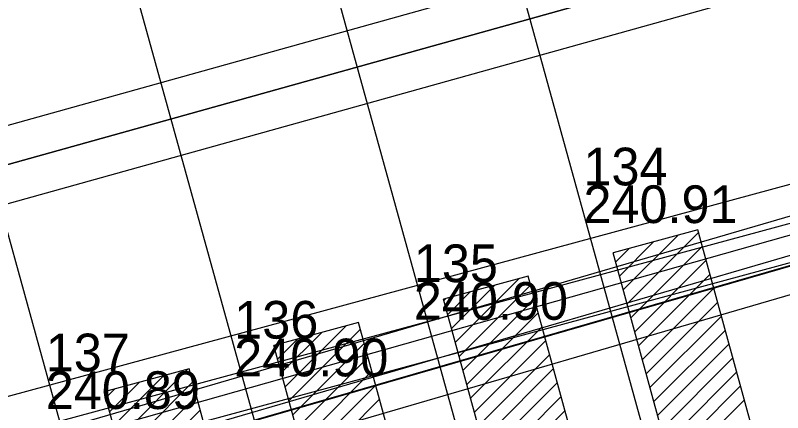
# Model space of a CAD drawing. Extents: x -599432 to -598680, y -1159407 to -1158632.
# Drawn here: x -599029.29 to -599023.18, y -1158877.07 to -1158873.91 of the extents above; entities that cross this region are included whole.
import ezdxf

# ---------------------------------------------------------------- set-up
doc = ezdxf.new("R2010")
doc.units = 0
for name, color, linetype in [('0004 VY - Body podrobné', 7, 'Continuous'), ('0005 VY - Body podrobné - čísla', 7, 'Continuous'), ('0006 VY - Body podrobné - výšky', 7, 'Continuous'), ('0063 ZA - Doprava - vodorovné značení', 7, 'Continuous'), ('0066 ZA - Doprava - DPMB - koleje', 7, 'Continuous'), ('0202 PV - MUNI', 7, 'Continuous'), ('0203 PV - MUNI - chránička', 7, 'Continuous'), ('0454 PV - O2 - kabel zaměřený', 7, 'Continuous'), ('0530 PV - T-mobile - optické kabely', 7, 'Continuous'), ('0552 PV - NETBOX - vedení', 7, 'Continuous'), ('0553 PV - NETBOX - chranička', 7, 'Continuous'), ('0650 PV - BKOM - buňky', 7, 'Continuous'), ('0652 PV - BKOM - kabely bez rozlišení', 7, 'Continuous'), ('0704 PV - ČD - kabely', 7, 'Continuous')]:
    doc.layers.add(name, color=color, linetype=linetype)

msp = doc.modelspace()

# ---------------------------------------------------------------- linework, layer by layer
at = {"layer": '0004 VY - Body podrobné'}
for p, q in [((-599024.77, -1158875.26), (-599024.77, -1158875.26)), ((-599026.12, -1158876.03), (-599026.12, -1158876.03)), ((-599027.55, -1158876.48), (-599027.55, -1158876.48)), ((-599029.05, -1158876.74), (-599029.05, -1158876.74))]:
    msp.add_line(p, q, dxfattribs=at)
at = {"layer": '0063 ZA - Doprava - vodorovné značení'}
for p, q in [((-599023.8584, -1158875.6129), (-599024.5336, -1158875.7973)), ((-599024.453, -1158876.0924), (-599024.0167, -1158875.6561)), ((-599024.4227, -1158876.2035), (-599023.8527, -1158875.6335)), ((-599022.5886, -1158880.2609), (-599023.8584, -1158875.6129)), ((-599024.4834, -1158875.9813), (-599024.2113, -1158875.7093)), ((-599024.5137, -1158875.8702), (-599024.4059, -1158875.7624)), ((-599024.3923, -1158876.3146), (-599023.8224, -1158875.7446)), ((-599023.2639, -1158880.4453), (-599024.5336, -1158875.7973)), ((-599024.362, -1158876.4256), (-599023.792, -1158875.8557)), ((-599024.3316, -1158876.5367), (-599023.7617, -1158875.9668)), ((-599025.2089, -1158875.9818), (-599025.8841, -1158876.1662)), ((-599025.7901, -1158876.5104), (-599025.2812, -1158876.0015)), ((-599023.9392, -1158880.6298), (-599025.2089, -1158875.9818)), ((-599025.8205, -1158876.3994), (-599025.4758, -1158876.0547)), ((-599025.7598, -1158876.6215), (-599025.1898, -1158876.0516)), ((-599024.3013, -1158876.6478), (-599023.7314, -1158876.0778)), ((-599025.8508, -1158876.2883), (-599025.6704, -1158876.1079)), ((-599024.6144, -1158880.8143), (-599025.8841, -1158876.1662)), ((-599025.8812, -1158876.1772), (-599025.865, -1158876.161)), ((-599025.7294, -1158876.7326), (-599025.1595, -1158876.1626)), ((-599024.271, -1158876.7589), (-599023.701, -1158876.1889)), ((-599025.6991, -1158876.8437), (-599025.1291, -1158876.2737)), ((-599024.2406, -1158876.8699), (-599023.6707, -1158876.3)), ((-599026.5594, -1158876.3507), (-599027.2347, -1158876.5352)), ((-599027.1447, -1158876.8644), (-599026.6579, -1158876.3776)), ((-599025.2897, -1158880.9987), (-599026.5594, -1158876.3507)), ((-599025.6687, -1158876.9547), (-599025.0988, -1158876.3848)), ((-599027.1751, -1158876.7533), (-599026.8525, -1158876.4308)), ((-599027.1144, -1158876.9755), (-599026.5444, -1158876.4056)), ((-599024.2103, -1158876.981), (-599023.6403, -1158876.4111)), ((-599027.2054, -1158876.6423), (-599027.0471, -1158876.4839)), ((-599027.084, -1158877.0866), (-599026.5141, -1158876.5166)), ((-599025.6384, -1158877.0658), (-599025.0685, -1158876.4959)), ((-599025.9649, -1158881.1832), (-599027.2347, -1158876.5352)), ((-599024.1799, -1158877.0921), (-599023.61, -1158876.5221)), ((-599027.0537, -1158877.1977), (-599026.4837, -1158876.6277)), ((-599025.6081, -1158877.1769), (-599025.0381, -1158876.6069)), ((-599024.1496, -1158877.2032), (-599023.5796, -1158876.6332)), ((-599027.9099, -1158876.7196), (-599028.5852, -1158876.9041)), ((-599028.4812, -1158877.2848), (-599027.9183, -1158876.7219)), ((-599026.6402, -1158881.3676), (-599027.9099, -1158876.7196)), ((-599027.0233, -1158877.3087), (-599026.4534, -1158876.7388)), ((-599025.5777, -1158877.288), (-599025.0078, -1158876.718)), ((-599024.1192, -1158877.3143), (-599023.5493, -1158876.7443)), ((-599028.5115, -1158877.1737), (-599028.1129, -1158876.7751)), ((-599028.5722, -1158876.9516), (-599028.502, -1158876.8814)), ((-599028.5419, -1158877.0627), (-599028.3075, -1158876.8282)), ((-599028.4508, -1158877.3959), (-599027.8809, -1158876.8259)), ((-599026.993, -1158877.4198), (-599026.423, -1158876.8499)), ((-599025.5474, -1158877.399), (-599024.9774, -1158876.8291)), ((-599024.0889, -1158877.4253), (-599023.5189, -1158876.8554)), ((-599027.3154, -1158881.5521), (-599028.5852, -1158876.9041)), ((-599028.4205, -1158877.507), (-599027.8505, -1158876.937)), ((-599025.517, -1158877.5101), (-599024.9471, -1158876.9402)), ((-599026.9627, -1158877.5309), (-599026.3927, -1158876.9609)), ((-599024.0586, -1158877.5364), (-599023.4886, -1158876.9665)), ((-599028.3901, -1158877.618), (-599027.8202, -1158877.0481)), ((-599025.4867, -1158877.6212), (-599024.9167, -1158877.0513))]:
    msp.add_line(p, q, dxfattribs=at)
at = {"layer": '0066 ZA - Doprava - DPMB - koleje'}
for p, q in [((-599026.9947, -1158867.4391), (-599013.0005, -1158918.0205)), ((-599028.37, -1158867.8196), (-599014.3759, -1158918.401)), ((-599029.8529, -1158868.2298), (-599015.8588, -1158918.8113)), ((-599031.2942, -1158868.6286), (-599017.3, -1158919.21))]:
    msp.add_line(p, q, dxfattribs=at)
at = {"layer": '0202 PV - MUNI'}
msp.add_lwpolyline([(-599146.6366, -1158922.9878), (-599125.8483, -1158917.7447), (-599099.1764, -1158910.8285), (-599079.1004, -1158904.889), (-599063.7152, -1158899.846), (-599061.634, -1158898.4051), (-599061.0656, -1158896.468), (-599061.7781, -1158890.9687), (-599061.2017, -1158889.9281), (-599056.1907, -1158887.5907), (-599053.9174, -1158887.4786), (-599048.5222, -1158885.3494), (-599047.3855, -1158884.4528), (-599040.0211, -1158881.2029), (-599032.6727, -1158878.6013), (-599020.5455, -1158875.0632), (-599018.4963, -1158874.7671), (-599015.6546, -1158876.8083), (-599014.9422, -1158877.8009)], dxfattribs=at)
at = {"layer": '0203 PV - MUNI - chránička'}
for p, q in [((-599032.7567, -1158878.3133), (-599020.6295, -1158874.7752)), ((-599032.5887, -1158878.8893), (-599020.4615, -1158875.3512))]:
    msp.add_line(p, q, dxfattribs=at)
at = {"layer": '0454 PV - O2 - kabel zaměřený'}
for points in [[(-599065.99, -1158901.17), (-599063.3, -1158900.18), (-599061.65, -1158898.45), (-599061.04, -1158896.51), (-599061.91, -1158890.95), (-599061.26, -1158889.87), (-599056.07, -1158887.58), (-599053.91, -1158887.47), (-599052.4, -1158886.85), (-599049.09, -1158885.94), (-599048.46, -1158885.4), (-599047.47, -1158884.55), (-599040.18, -1158881.35), (-599032.72, -1158878.67), (-599020.59, -1158875.17), (-599018.58, -1158874.88), (-599016.36, -1158876.44), (-599015.76, -1158876.86), (-599014.99, -1158877.89), (-599012.08, -1158888.14), (-599011.3, -1158889.38), (-599007.9, -1158892.89), (-599006.6, -1158893.35), (-598996.83, -1158890.81)], [(-599032.72, -1158878.67), (-599020.59, -1158875.17)]]:
    msp.add_lwpolyline(points, dxfattribs=at)
at = {"layer": '0530 PV - T-mobile - optické kabely'}
msp.add_lwpolyline([(-599020.585, -1158875.165), (-599032.721, -1158878.667)], dxfattribs=at)
at = {"layer": '0552 PV - NETBOX - vedení'}
msp.add_lwpolyline([(-599006.06, -1158869.51), (-599006.06, -1158869.51), (-599007.15, -1158869.17), (-599007.15, -1158869.17), (-599008.89, -1158870.73), (-599009.02, -1158871.08), (-599010.62, -1158871.57), (-599015.34, -1158873.36), (-599021.01, -1158874.99), (-599029.72, -1158877.35), (-599032.35, -1158878.18), (-599038.52, -1158879.88), (-599044.56, -1158881.49), (-599050.4, -1158884.03), (-599052.74, -1158885.29), (-599055.15, -1158886.37), (-599057.94, -1158887.57), (-599060.68, -1158888.43), (-599062.55, -1158889.31)], dxfattribs=at)
at = {"layer": '0553 PV - NETBOX - chranička'}
msp.add_lwpolyline([(-599015.4348, -1158873.0751), (-599021.0907, -1158874.701), (-599029.8044, -1158877.0621), (-599032.435, -1158877.8922), (-599038.5985, -1158879.5904), (-599044.659, -1158881.2059), (-599050.53, -1158883.7594), (-599053.1483, -1158885.1442), (-599055.2706, -1158886.0953), (-599058.0445, -1158887.2884), (-599060.7893, -1158888.1499), (-599062.6777, -1158889.0386), (-599062.4223, -1158889.5814), (-599060.5707, -1158888.7101), (-599057.8355, -1158887.8516), (-599055.0294, -1158886.6447), (-599052.3317, -1158885.4358), (-599050.27, -1158884.3006), (-599044.461, -1158881.7741), (-599038.4415, -1158880.1696), (-599032.265, -1158878.4678), (-599029.6356, -1158877.6379), (-599020.9293, -1158875.279), (-599015.2452, -1158873.6449)], dxfattribs=at)
at = {"layer": '0650 PV - BKOM - buňky'}
for p, q in [((-599034.191, -1158876.131), (-599020.461, -1158872.301)), ((-599034.191, -1158876.131), (-599020.461, -1158872.301)), ((-599034.029, -1158876.709), (-599020.299, -1158872.879)), ((-599034.029, -1158876.709), (-599020.299, -1158872.879))]:
    msp.add_line(p, q, dxfattribs=at)
at = {"layer": '0652 PV - BKOM - kabely bez rozlišení'}
for points in [[(-599019.95, -1158872.38), (-599020.38, -1158872.59), (-599034.11, -1158876.42), (-599034.75, -1158875.39), (-599039.03, -1158861.54), (-599042.74, -1158848.47), (-599042.28, -1158847.4), (-599041.79, -1158847.4)], [(-599069.54, -1158906.27), (-599056.01, -1158902.46), (-599042.94, -1158898.82), (-599036.88, -1158897.21), (-599035.9, -1158896.65), (-599035.19, -1158895.15), (-599033.43, -1158892.94), (-599032.55, -1158892.85), (-599032.38, -1158891.47), (-599031.43, -1158887.7), (-599033.39, -1158880.98), (-599034.34, -1158877.53), (-599034.11, -1158876.42), (-599020.38, -1158872.59), (-599019.95, -1158872.38), (-599019.48, -1158873.04), (-599018.91, -1158874.17), (-599016.73, -1158875.93), (-599015.62, -1158876.75), (-599013.57, -1158877.37), (-599011.16, -1158877.03), (-599007.55, -1158875.71), (-599006.793, -1158874.464)]]:
    msp.add_lwpolyline(points, dxfattribs=at)
at = {"layer": '0704 PV - ČD - kabely'}
msp.add_lwpolyline([(-598961.1998, -1158881.213), (-599006.8409, -1158893.8814), (-599007.9998, -1158893.3892), (-599012.4449, -1158888.2457), (-599014.7944, -1158877.5617), (-599015.5723, -1158876.5616), (-599018.4457, -1158874.6248), (-599020.4301, -1158874.8947), (-599032.7968, -1158878.3872), (-599047.1639, -1158884.134), (-599048.6403, -1158885.0865), (-599049.561, -1158885.3882), (-599050.6564, -1158886.3724), (-599052.3709, -1158886.6423), (-599054.1807, -1158887.3884), (-599056.3556, -1158887.4043), (-599061.2213, -1158889.6983), (-599062.0071, -1158890.8333), (-599061.1578, -1158896.5405), (-599061.8246, -1158898.4296), (-599063.5073, -1158900.1441), (-599114.0221, -1158914.7334)], dxfattribs=at)

# ---------------------------------------------------------------- texts
at = {"layer": '0005 VY - Body podrobné - čísla'}
for s, p in [('134', (-599024.77, -1158875.26)), ('135', (-599026.12, -1158876.03)), ('136', (-599027.55, -1158876.48)), ('137', (-599029.05, -1158876.74))]:
    msp.add_text(s, height=0.3, dxfattribs=at).set_placement(p)
at = {"layer": '0006 VY - Body podrobné - výšky'}
for s, p in [('240.91', (-599024.77, -1158875.56)), ('240.90', (-599026.12, -1158876.33)), ('240.90', (-599027.55, -1158876.78)), ('240.89', (-599029.05, -1158877.04))]:
    msp.add_text(s, height=0.3, dxfattribs=at).set_placement(p)

doc.saveas('drawing.dxf')
